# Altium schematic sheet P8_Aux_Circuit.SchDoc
size 368 x 228 mm
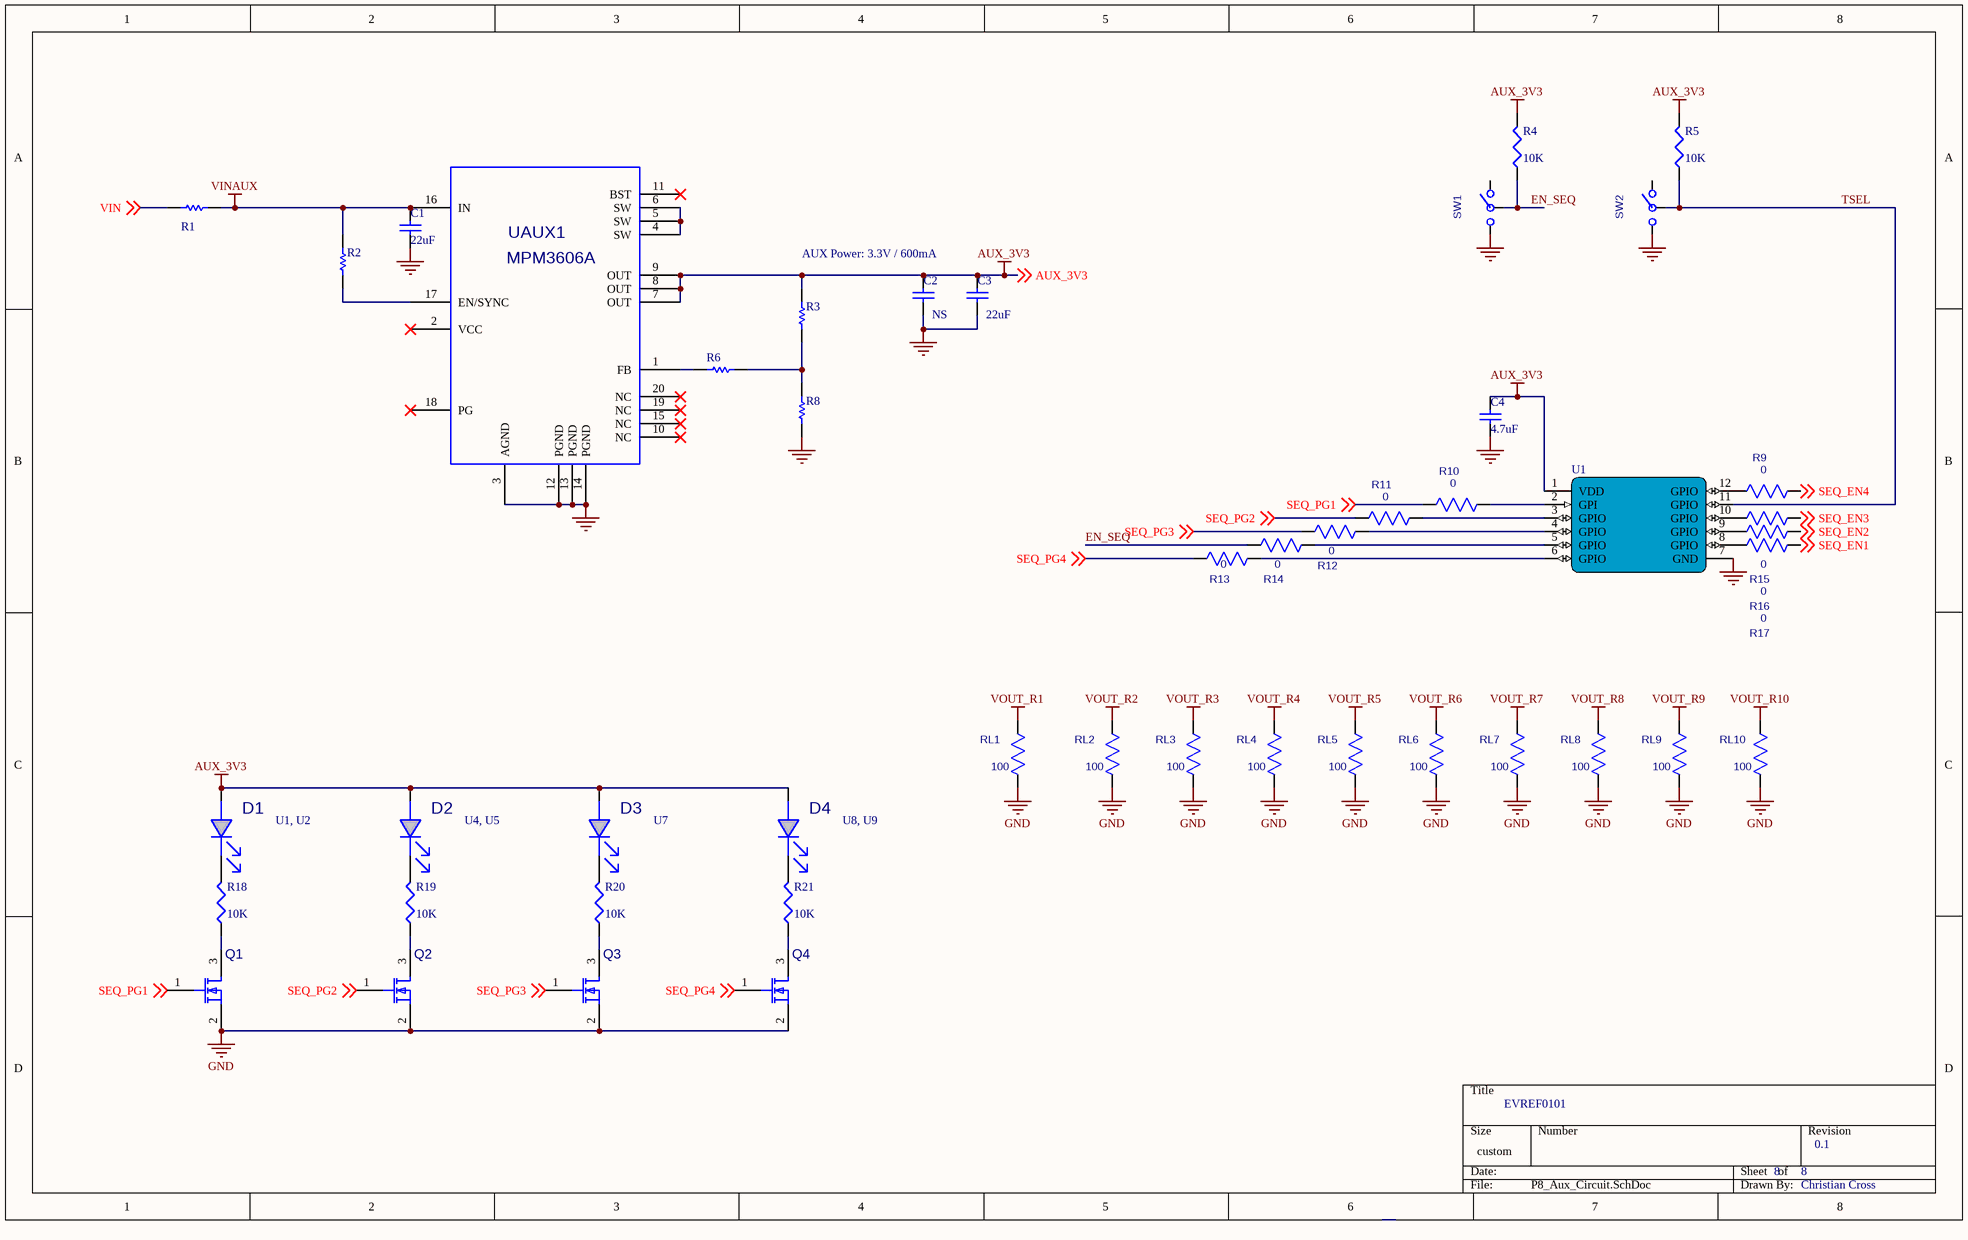
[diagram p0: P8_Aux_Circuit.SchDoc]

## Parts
C1  22uF  [CAP0805]
C2  NS  [CAP0805]
C3  22uF  [CAP0805]
C4  4.7uF  [CAP0805]
D1  BL-HGB35A-TRB  [LED/SMD/0805]  (value not drawn)
D2  BL-HGB35A-TRB  [LED/SMD/0805]  (value not drawn)
D3  BL-HGB35A-TRB  [LED/SMD/0805]  (value not drawn)
D4  BL-HGB35A-TRB  [LED/SMD/0805]  (value not drawn)
Q1  *  [ZVN3320/SOT23]  (value not drawn)
Q2  *  [ZVN3320/SOT23]  (value not drawn)
Q3  *  [ZVN3320/SOT23]  (value not drawn)
Q4  *  [ZVN3320/SOT23]  (value not drawn)
R1  10mohm  [RES/0805]  (value not drawn)
R2  100K  [RES/0603]  (value not drawn)
R3  75k  [RES/0603]  (value not drawn)
R4  10K  [RES/0603]
R5  10K  [RES/0603]
R6  0ohm  [RES/0603]  (value not drawn)
R8  24k  [RES/0603]  (value not drawn)
R9  0  [RES0603]
R10  0  [RES0603]
R11  0  [RES0603]
R12  0  [RES0603]
R13  0  [RES0603]
R14  0  [RES0603]
R15  0  [RES0603]
R16  0  [RES0603]
R17  0  [RES0603]
R18  10K  [RES/0603]
R19  10K  [RES/0603]
R20  10K  [RES/0603]
R21  10K  [RES/0603]
RL1  100  [RES/0805]
RL2  100  [RES/0805]
RL3  100  [RES/0805]
RL4  100  [RES/0805]
RL5  100  [RES/0805]
RL6  100  [RES/0805]
RL7  100  [RES/0805]
RL8  100  [RES/0805]
RL9  100  [RES/0805]
RL10  100  [RES/0805]
SW1  *  [JUMPER/3PIN-WE450301014042]  (value not drawn)
SW2  *  [JUMPER/3PIN-WE450301014042]  (value not drawn)
U1  SLG46120  [SLG4MP41885]  (value not drawn)
UAUX1  MPM3606A  [QFN20-3X5MM]

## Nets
AUX_3V3: C2.2 C3.2 C4.2 D1.2 D2.2 D3.2 D4.2 R3.2 R4.2 R5.2 U1.1(VDD) UAUX1.7(OUT) UAUX1.8(OUT) UAUX1.9(OUT) ; off-sheet AUX_3V3
GND: C1.1 C2.1 C3.1 C4.1 Q1.2(S) Q2.2(S) Q3.2(S) Q4.2(S) R8.1 RL1.2 RL2.2 RL3.2 RL4.2 RL5.2 RL6.2 RL7.2 RL8.2 RL9.2 RL10.2 SW1.1 SW2.1 U1.7(GND) UAUX1.3(AGND) UAUX1.12(PGND) UAUX1.13(PGND) UAUX1.14(PGND)
VINAUX: C1.2 R1.2 R2.1 UAUX1.16(IN)
VOUT_R1: RL1.1
VOUT_R2: RL2.1
VOUT_R3: RL3.1
VOUT_R4: RL4.1
VOUT_R5: RL5.1
VOUT_R6: RL6.1
VOUT_R7: RL7.1
VOUT_R8: RL8.1
VOUT_R9: RL9.1
VOUT_R10: RL10.1
EN_SEQ: R4.1 R14.1 SW1.2
SEQ_EN1: R17.2 ; off-sheet SEQ_EN1
SEQ_EN2: R16.2 ; off-sheet SEQ_EN2
SEQ_EN3: R15.2 ; off-sheet SEQ_EN3
SEQ_EN4: R9.2 ; off-sheet SEQ_EN4
SEQ_PG1: Q1.1(G) R10.1 ; off-sheet SEQ_PG1
SEQ_PG2: Q2.1(G) R11.1 ; off-sheet SEQ_PG2
SEQ_PG3: Q3.1(G) R12.1 ; off-sheet SEQ_PG3
SEQ_PG4: Q4.1(G) R13.1 ; off-sheet SEQ_PG4
TSEL: R5.1 SW2.2 U1.11(GPIO)
VIN: R1.1 ; off-sheet VIN
NetD1_1: D1.1 R18.2
NetD2_1: D2.1 R19.2
NetD3_1: D3.1 R20.2
NetD4_1: D4.1 R21.2
NetQ1_3: Q1.3(D) R18.1
NetQ2_3: Q2.3(D) R19.1
NetQ3_3: Q3.3(D) R20.1
NetQ4_3: Q4.3(D) R21.1
NetR2_2: R2.2 UAUX1.17(EN/SYNC)
NetR3_1: R3.1 R6.2 R8.2
NetR6_1: R6.1 UAUX1.1(FB)
NetR9_1: R9.1 U1.12(GPIO)
NetR10_2: R10.2 U1.2(GPI)
NetR11_2: R11.2 U1.3(GPIO)
NetR12_2: R12.2 U1.4(GPIO)
NetR13_2: R13.2 U1.6(GPIO)
NetR14_2: R14.2 U1.5(GPIO)
NetR15_1: R15.1 U1.10(GPIO)
NetR16_1: R16.1 U1.9(GPIO)
NetR17_1: R17.1 U1.8(GPIO)
NetUAUX1_4: UAUX1.4(SW) UAUX1.5(SW) UAUX1.6(SW)

Not connected (* = marked no-connect by the designer): SW1 3; SW2 3; UAUX1 2(VCC)* 10(NC)* 11(BST)* 15(NC)* 18(PG)* 19(NC)* 20(NC)*

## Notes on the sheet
- AUX Power: 3.3V / 600mA
- U1, U2
- U4, U5
- U7
- U8, U9
- EVREF0101
- 8
- 0.1
- Christian Cross

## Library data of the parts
C1-C4 = Cap: Capacitor
D1-D4 = 19.0004: LED;쫄밟; Manufacturer P/N: {Manufacturer P/N}; Manufacturer: {Manufacturer}; Manufacture: BRIGHT LED; Pid: 38; Out_Num: 0
Q1-Q4 = ZVN3320/SOT23: {Description}; Manufacturer: {Manufacturer}; Manufacturer P/N: {Manufacturer P/N}
R1-R3 R6 R8 = Res1: Resistor
R4 R5 R18-R21 = Res3: Resistor
R9-R17 RL1-RL10 = RES2512: {Description}; Manufacturer P/N: {Manufacturer P/N}; Manufacturer: {Manufacturer}
SW1 SW2 = SWITCH_SPDT_WE: {Description}; Manufacturer: {Manufacturer}; Manufacturer P/N: {Manufacturer P/N}
U1 = SLG46120: GreenPAK Programmable Mixed Signal Array
UAUX1 = MPM3630A: 18V/3A DC/DC Module Synchronous Step-Down Regulator; Manufacturer: {Manufacturer}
